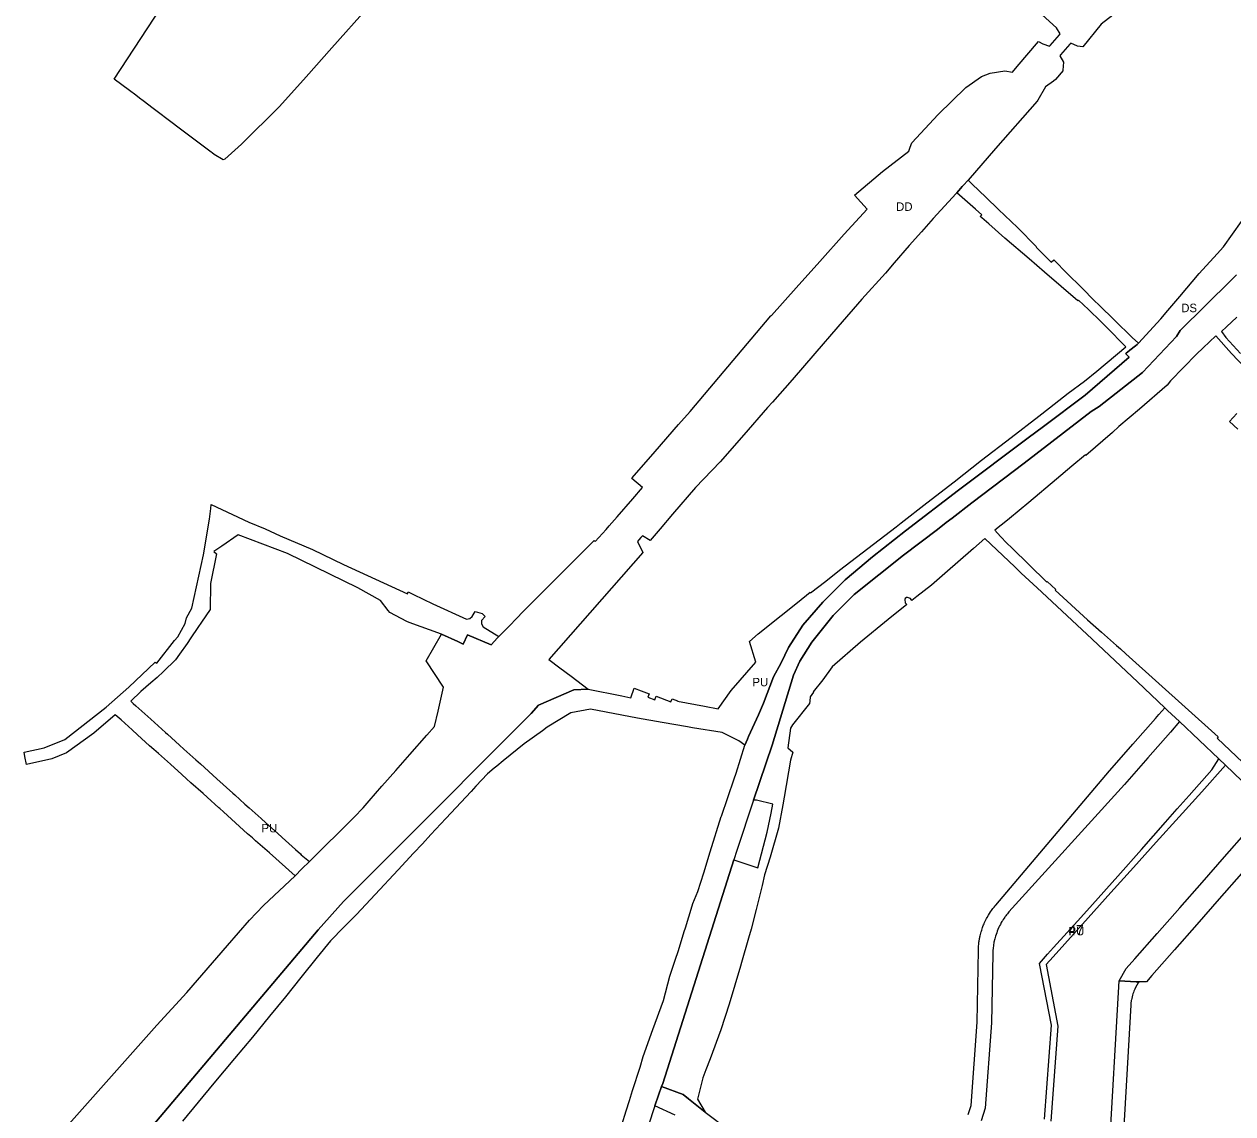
# Model space of a CAD drawing. Extents: x -537034 to -534353, y -1176562 to -1173176.
# Drawn here: x -536869 to -536157, y -1175906 to -1175264 of the extents above; entities that cross this region are included whole.
import ezdxf

# ---------------------------------------------------------------- set-up
doc = ezdxf.new("R2010")
doc.units = 0
for name, color, linetype in [('90320013', 7, 'Continuous'), ('90320023', 7, 'Continuous'), ('90330013', 7, 'Continuous'), ('90450013', 7, 'Continuous'), ('90450023', 7, 'Continuous'), ('ID_navrh', 7, 'Continuous')]:
    doc.layers.add(name, color=color, linetype=linetype)

msp = doc.modelspace()

# ---------------------------------------------------------------- linework, layer by layer
at = {"layer": '90320013'}
for points in [[(-536519.66, -1175920.91), (-536514.46, -1175904.33), (-536512.56, -1175898.3), (-536510.72, -1175892.44), (-536506.23, -1175878.56), (-536504.53, -1175872.39), (-536498.83, -1175856.51), (-536492.59, -1175839.22), (-536488.8, -1175824.91), (-536485.61, -1175815.62), (-536483.62, -1175809.83), (-536480.29, -1175798.68), (-536479.62, -1175796.43), (-536475.64, -1175783.55), (-536475.23, -1175782.21), (-536472.36, -1175775.09), (-536468.71, -1175764.01), (-536465.05, -1175751.7), (-536458.51, -1175730.84), (-536458.43, -1175730.59), (-536450.82, -1175708.65), (-536449.79, -1175705.35), (-536444.62, -1175688.79), (-536443.04, -1175685.26), (-536442.34, -1175683.69), (-536436.61, -1175670.86), (-536433.52, -1175663.95), (-536427.64, -1175648.47), (-536423.18, -1175640.21), (-536418.84, -1175631.19), (-536410.33, -1175618.03), (-536398.71, -1175604.41), (-536385.41, -1175591.37), (-536369.41, -1175577.67), (-536349.95, -1175562.45), (-536318.57, -1175538.4), (-536277.56, -1175507.64), (-536268.45, -1175500.89), (-536243.96, -1175482.32), (-536217.96, -1175459.97), (-536220.11, -1175458.05), (-536219.83, -1175457.6), (-536217.91, -1175456.09), (-536217.72, -1175455.94), (-536214.26, -1175453.22), (-536213.33, -1175452.49), (-536212.48, -1175451.82), (-536199.34, -1175437.32), (-536195.17, -1175432.47), (-536188.12, -1175424.25), (-536176.87, -1175410.74), (-536166.1, -1175399.03), (-536162.37, -1175394.92), (-536151.81, -1175379.91)], [(-536154.83, -1175411.41), (-536157.86, -1175414.59), (-536187.97, -1175444.22), (-536190.24, -1175447.73), (-536210.28, -1175468.95), (-536235.72, -1175489.07), (-536240.39, -1175492.07), (-536279.99, -1175522.59), (-536310.74, -1175545.81), (-536322.43, -1175554.85), (-536325.83, -1175557.48), (-536331.05, -1175561.51), (-536351.16, -1175576.73), (-536380.2, -1175599.97), (-536392.55, -1175612.31), (-536405.08, -1175628.03), (-536412.09, -1175639.32), (-536415.88, -1175647.57), (-536428.44, -1175688.76), (-536439.57, -1175721.17), (-536449.31, -1175750.95), (-536451.05, -1175756.43), (-536492.97, -1175888.35), (-536493.8, -1175890.01), (-536495.51, -1175895.12), (-536497.61, -1175901.43), (-536501.59, -1175913.34)]]:
    msp.add_lwpolyline(points, dxfattribs=at)
at = {"layer": '90320023'}
msp.add_lwpolyline([(-536666.61, -1175253.57), (-536687.97, -1175277.68), (-536703.1, -1175294.68), (-536718.93, -1175312.13), (-536741.24, -1175334.42), (-536751.07, -1175343.25), (-536752.13, -1175343.71), (-536757.4, -1175340.47), (-536758.57, -1175339.58), (-536759.2, -1175339.11), (-536765.49, -1175334.36), (-536770.11, -1175330.87), (-536779.51, -1175323.77), (-536781.4, -1175322.34), (-536793.39, -1175313.28), (-536799.27, -1175308.85), (-536801.44, -1175307.2), (-536803.58, -1175305.58), (-536807.23, -1175302.83), (-536816.28, -1175295.99), (-536776.99, -1175235.99)], dxfattribs=at)
at = {"layer": '90330013'}
for points in [[(-536846.2, -1175915.82), (-536791.26, -1175853.94), (-536773.58, -1175834.53), (-536749.56, -1175806.92), (-536736.63, -1175791.89), (-536728.37, -1175783.23), (-536709.68, -1175765.75), (-536705.63, -1175761.74), (-536701.22, -1175757.38), (-536674.81, -1175731.24), (-536669.64, -1175725.77), (-536666.05, -1175721.61), (-536658.6, -1175712.98), (-536650.32, -1175703.64), (-536642.03, -1175694.23), (-536632.12, -1175682.89), (-536627.48, -1175677.77), (-536625.43, -1175668.78), (-536622.16, -1175654.48), (-536632.47, -1175639.06), (-536623.43, -1175623.26), (-536613.76, -1175627.61), (-536610.57, -1175629.19), (-536607.97, -1175623.66), (-536594.17, -1175629.6), (-536590.32, -1175625.47), (-536589.63, -1175624.73), (-536582.21, -1175617.2), (-536580.31, -1175615.27), (-536574, -1175608.87), (-536533.39, -1175568.16), (-536532.78, -1175568.71), (-536526.41, -1175561.66), (-536524.48, -1175559.53), (-536521.41, -1175555.97), (-536519.88, -1175554.19), (-536510.62, -1175543.44), (-536504.9, -1175536.8), (-536511.29, -1175531.46), (-536511.02, -1175531.18), (-536497.42, -1175515.55), (-536483.59, -1175499.65), (-536476.88, -1175491.96), (-536429.2, -1175435.56), (-536428.82, -1175435.33), (-536414.4, -1175419.11), (-536400.46, -1175403.61), (-536385.98, -1175387.51), (-536372.45, -1175372.79), (-536379.99, -1175364.45), (-536363.36, -1175350.59), (-536348.02, -1175338.47), (-536347.12, -1175336.1), (-536346.17, -1175333.57), (-536330.65, -1175316.94), (-536314.41, -1175300.96), (-536305.13, -1175294.43), (-536299.98, -1175292.46), (-536291.26, -1175291.15), (-536286.76, -1175291.86), (-536284.03, -1175288.64), (-536271.52, -1175273.92), (-536269.03, -1175275.21), (-536265.02, -1175276.59), (-536264.68, -1175276.25), (-536259.12, -1175269.87), (-536258.63, -1175269.32), (-536260.91, -1175265.77), (-536271.48, -1175256.23)], [(-536227.77, -1175258.32), (-536234.54, -1175263.73), (-536245.43, -1175277.08), (-536248.56, -1175276.64), (-536252.42, -1175274.85), (-536252.93, -1175275.41), (-536258.45, -1175281.76), (-536258.98, -1175282.35), (-536256.81, -1175285.98), (-536257.21, -1175290.77), (-536256.94, -1175290.98), (-536261.38, -1175296.33), (-536262.6, -1175297.2), (-536267.4, -1175300.62), (-536271.83, -1175308.52), (-536272.24, -1175308.98), (-536296.79, -1175336.88), (-536313.02, -1175355.71), (-536315.99, -1175358.85), (-536316.44, -1175359.37), (-536318.47, -1175361.7), (-536319.66, -1175363.06), (-536320, -1175363.42), (-536333.58, -1175378.3), (-536340.48, -1175386.07), (-536347.65, -1175394.16), (-536356.49, -1175404.43), (-536361.6, -1175410.37), (-536375.55, -1175425.83), (-536389.71, -1175442.02), (-536403.38, -1175457.84), (-536416.7, -1175473.42), (-536428.33, -1175486.62), (-536431.21, -1175489.75), (-536445.18, -1175505.86), (-536459.13, -1175521.73), (-536473.75, -1175536.92), (-536487.22, -1175552.59), (-536494.58, -1175561.14), (-536500.44, -1175568.03), (-536504.84, -1175565.28), (-536505.83, -1175566.38), (-536507.02, -1175567.7), (-536507.91, -1175568.69), (-536504.76, -1175575.16), (-536560.04, -1175638.23), (-536553.54, -1175643.15), (-536547.03, -1175648.06), (-536536.94, -1175655.74), (-536545.35, -1175656.1), (-536566.3, -1175665.09), (-536570.53, -1175670.13), (-536586.48, -1175686.06), (-536635.97, -1175735.72), (-536681.17, -1175780.92), (-536696.11, -1175797.67), (-536798.9, -1175919.35)]]:
    msp.add_lwpolyline(points, dxfattribs=at)
at = {"layer": '90450013'}
for points in [[(-536798.9, -1175919.35), (-536696.11, -1175797.67), (-536681.17, -1175780.92), (-536635.97, -1175735.72), (-536586.48, -1175686.06), (-536570.53, -1175670.13), (-536566.3, -1175665.09), (-536545.35, -1175656.1), (-536536.94, -1175655.74), (-536517.13, -1175659.73), (-536511.84, -1175660.79), (-536509.74, -1175655.18), (-536505.74, -1175656.72), (-536501.02, -1175658.45), (-536501.75, -1175660.46), (-536497.69, -1175661.96), (-536496.94, -1175659.94), (-536488.15, -1175663.14), (-536487.36, -1175661.38), (-536484.19, -1175662.58), (-536484.22, -1175662.75), (-536468.28, -1175665.81), (-536460.22, -1175667.35), (-536452.58, -1175656.54), (-536438.2, -1175639.85), (-536441.85, -1175627.58), (-536436.79, -1175623.18), (-536423.27, -1175612.27), (-536413.63, -1175604.6), (-536406.06, -1175598.58), (-536405.88, -1175599.04), (-536396.81, -1175592.01), (-536388.78, -1175585.64), (-536372.09, -1175572.8), (-536355.44, -1175559.96), (-536352.38, -1175557.58), (-536337.3, -1175545.98), (-536321.26, -1175533.57), (-536305.05, -1175520.71), (-536287.61, -1175507.42), (-536271.22, -1175494.78), (-536265.06, -1175489.95), (-536253.95, -1175481.24), (-536244.48, -1175474.06), (-536237.18, -1175468.25), (-536220.03, -1175453.93), (-536222.14, -1175451.77), (-536229.53, -1175444.21), (-536234.79, -1175438.94), (-536242.05, -1175431.84), (-536247.92, -1175426.47), (-536248.3, -1175426.83), (-536267.93, -1175409.82), (-536276.93, -1175402.02), (-536291.35, -1175389.78), (-536300.73, -1175381.3), (-536304.93, -1175377.81), (-536305.8, -1175377.11), (-536304.81, -1175376.15), (-536308.59, -1175372.82), (-536319.66, -1175363.06), (-536318.47, -1175361.7), (-536316.44, -1175359.37), (-536315.99, -1175358.85), (-536313.02, -1175355.71), (-536310.63, -1175358.07), (-536302.54, -1175365.62), (-536295.1, -1175372.83), (-536283.95, -1175383.63), (-536272.71, -1175395.02), (-536272.91, -1175395.19), (-536263.98, -1175403.91), (-536262.48, -1175402.52), (-536254.37, -1175410.87), (-536246.41, -1175418.7), (-536245.74, -1175419.37), (-536238.66, -1175426.53), (-536235.8, -1175429.32), (-536226.72, -1175438.18), (-536216.31, -1175448.44), (-536212.48, -1175451.82), (-536213.33, -1175452.49), (-536214.26, -1175453.22), (-536217.72, -1175455.94), (-536217.91, -1175456.09), (-536219.83, -1175457.6), (-536220.11, -1175458.05), (-536217.96, -1175459.97), (-536243.96, -1175482.32), (-536268.45, -1175500.89), (-536277.56, -1175507.64), (-536318.57, -1175538.4), (-536349.95, -1175562.45), (-536369.41, -1175577.67), (-536385.41, -1175591.37), (-536398.71, -1175604.41), (-536410.33, -1175618.03), (-536418.84, -1175631.19), (-536423.18, -1175640.21), (-536427.64, -1175648.47), (-536433.52, -1175663.95), (-536436.61, -1175670.86), (-536442.34, -1175683.69), (-536443.04, -1175685.26), (-536444.62, -1175688.79), (-536448.08, -1175686.22), (-536457.91, -1175681.22), (-536475.34, -1175678.45), (-536478.39, -1175677.96), (-536493.26, -1175675.35), (-536507.93, -1175672.77), (-536535.65, -1175667.47), (-536547.15, -1175669.72), (-536561.06, -1175678.16), (-536563.89, -1175680.22), (-536574.63, -1175688.07), (-536587.03, -1175697.96), (-536590.8, -1175701.08), (-536592.36, -1175702.37), (-536596.27, -1175705.6), (-536603.11, -1175712.96), (-536605.99, -1175716.06), (-536620.82, -1175732.03), (-536629.61, -1175741.5), (-536634.65, -1175746.92), (-536639.8, -1175752.47), (-536648.87, -1175762.23), (-536662.43, -1175776.83), (-536673.39, -1175788.63), (-536678.56, -1175793.79), (-536682.84, -1175798.07), (-536686.9, -1175802.13), (-536688.89, -1175804.11), (-536696.58, -1175813.74), (-536706.21, -1175825.8), (-536715.29, -1175837.15), (-536724.7, -1175848.63), (-536734.85, -1175860.84), (-536745.41, -1175873.54), (-536757.5, -1175888.08), (-536766.77, -1175899.23), (-536776.04, -1175910.38)], [(-536137.07, -1175723.72), (-536161.26, -1175700.56), (-536165.13, -1175696.86), (-536188.42, -1175674.83), (-536195.39, -1175668.24), (-536197.03, -1175666.69), (-536213.24, -1175651.35), (-536242.96, -1175623.24), (-536272.28, -1175596.08), (-536281.78, -1175587.31), (-536285.38, -1175583.66), (-536303.1, -1175566.86), (-536309.84, -1175572.9), (-536326.67, -1175587.47), (-536334.66, -1175594.33), (-536343.13, -1175601.15), (-536346.06, -1175603.45), (-536346.95, -1175602.29), (-536348.75, -1175601.63), (-536349.29, -1175601.72), (-536350.06, -1175602.36), (-536350.29, -1175602.89), (-536350.09, -1175604.75), (-536349.14, -1175605.89), (-536360.15, -1175614.65), (-536376.48, -1175628.12), (-536393.04, -1175642.64), (-536398.67, -1175650.18), (-536404.31, -1175657.23), (-536404.05, -1175657.58), (-536406.12, -1175660.23), (-536406.33, -1175662.83), (-536406.45, -1175664.29), (-536416.48, -1175676.82), (-536417.58, -1175678.72), (-536419.26, -1175690.31), (-536416.33, -1175692.99), (-536417.59, -1175697.58), (-536421.44, -1175719.49), (-536422.23, -1175723.99), (-536424.7, -1175737.67), (-536429.73, -1175754.77), (-536433.07, -1175765.28), (-536434.3, -1175771.54), (-536437.89, -1175785.71), (-536440.93, -1175797.21), (-536442.34, -1175802.56), (-536446.58, -1175817), (-536447.2, -1175819.1), (-536453.87, -1175841.56), (-536458.78, -1175856.58), (-536465.03, -1175873.79), (-536467.59, -1175880.27), (-536469.41, -1175884.86), (-536470.92, -1175891.24), (-536472.39, -1175897.49), (-536467.96, -1175905.16), (-536477.8, -1175897.3), (-536480.96, -1175894.78), (-536493.8, -1175890.01), (-536492.97, -1175888.35), (-536451.05, -1175756.43), (-536436.96, -1175761.16), (-536431.49, -1175740.04), (-536429.1, -1175728.93), (-536428.05, -1175723.51), (-536437.66, -1175721.11), (-536439.57, -1175721.17), (-536428.44, -1175688.76), (-536415.88, -1175647.57), (-536412.09, -1175639.32), (-536405.08, -1175628.03), (-536392.55, -1175612.31), (-536380.2, -1175599.97), (-536351.16, -1175576.73), (-536331.05, -1175561.51), (-536325.83, -1175557.48), (-536322.43, -1175554.85), (-536310.74, -1175545.81), (-536279.99, -1175522.59), (-536240.39, -1175492.07), (-536235.72, -1175489.07), (-536210.28, -1175468.95), (-536190.24, -1175447.73), (-536187.97, -1175444.22), (-536157.86, -1175414.59), (-536154.83, -1175411.41)], [(-536154.62, -1175436.42), (-536160.63, -1175442.04), (-536163.57, -1175444.87), (-536161.02, -1175448.4), (-536152.52, -1175457.9)], [(-536145.9, -1175470.18), (-536157.81, -1175457.83), (-536166.96, -1175447.43), (-536174.37, -1175454.52), (-536178.34, -1175458.15), (-536193.76, -1175473.93), (-536195.57, -1175476.41), (-536212.02, -1175490.57), (-536224.18, -1175500.97), (-536227.97, -1175504.42), (-536243.58, -1175517.91), (-536243.83, -1175517.63), (-536251.86, -1175524.3), (-536260.88, -1175531.83), (-536277.28, -1175545.71), (-536288.67, -1175555.08), (-536289.84, -1175556.05), (-536297.26, -1175561.99), (-536293.97, -1175565.69), (-536290.17, -1175569.66), (-536287.29, -1175572.46), (-536266.71, -1175592.48), (-536266.4, -1175592.18), (-536261.26, -1175596.93), (-536261.61, -1175597.28), (-536242.55, -1175614.82), (-536234.33, -1175622.13), (-536225.43, -1175630.05), (-536223.22, -1175632.01), (-536220.01, -1175634.87), (-536165.54, -1175683.92), (-536166.27, -1175684.73), (-536135.96, -1175713.3)], [(-536153.95, -1175502.45), (-536158.95, -1175497.88), (-536154.68, -1175493.22)], [(-536151.76, -1175764.43), (-536164.97, -1175779.44), (-536178.18, -1175794.46), (-536191.39, -1175809.48), (-536204.6, -1175824.5), (-536207.91, -1175828.28), (-536212.4, -1175828.28), (-536213.92, -1175828.28), (-536223.98, -1175827.73), (-536219.75, -1175820.53), (-536214.67, -1175814.75), (-536201.46, -1175799.73), (-536188.25, -1175784.71), (-536175.04, -1175769.7), (-536161.83, -1175754.68), (-536148.62, -1175739.66)]]:
    msp.add_lwpolyline(points, dxfattribs=at)
msp.add_lwpolyline([(-536759.14, -1175546.95), (-536746.47, -1175552.78), (-536736.91, -1175557.23), (-536727.32, -1175561.29), (-536718.49, -1175565.39), (-536699.5, -1175573.46), (-536681.23, -1175582.22), (-536662.36, -1175590.8), (-536643.39, -1175599.45), (-536642.94, -1175598.37), (-536639.79, -1175599.9), (-536628.44, -1175605.4), (-536608.62, -1175614.38), (-536606.62, -1175614.07), (-536605.3, -1175612.9), (-536603.52, -1175610.04), (-536599.34, -1175611.14), (-536597.56, -1175612.88), (-536599.82, -1175615.2), (-536599.89, -1175617.24), (-536598.9, -1175619.06), (-536589.63, -1175624.73), (-536590.32, -1175625.47), (-536594.17, -1175629.6), (-536607.97, -1175623.66), (-536610.57, -1175629.19), (-536613.76, -1175627.61), (-536623.43, -1175623.26), (-536642.39, -1175616.44), (-536643.86, -1175615.91), (-536653.91, -1175610.57), (-536654.82, -1175609.37), (-536659.38, -1175603.38), (-536672.73, -1175595.94), (-536714.23, -1175575.68), (-536743.31, -1175564.8), (-536752.82, -1175571.39), (-536756.99, -1175574.28), (-536757.55, -1175574.67), (-536756.05, -1175575.87), (-536759.54, -1175593.44), (-536759.8, -1175608.87), (-536764.75, -1175616.19), (-536766.93, -1175619.43), (-536771.12, -1175625.57), (-536773.32, -1175628.81), (-536777.81, -1175635.2), (-536780.16, -1175638.55), (-536787.27, -1175645.35), (-536791.04, -1175648.95), (-536794.76, -1175652.08), (-536800.66, -1175657.18), (-536806.57, -1175662.74), (-536806.21, -1175663.08), (-536805.07, -1175664.17), (-536803.64, -1175665.54), (-536794.65, -1175673.53), (-536786.11, -1175681.27), (-536784.91, -1175682.36), (-536777.74, -1175688.84), (-536775.31, -1175691.04), (-536768.18, -1175697.45), (-536765.5, -1175699.86), (-536755.85, -1175708.53), (-536746.34, -1175717.05), (-536745.23, -1175718.05), (-536739.26, -1175723.46), (-536736.75, -1175725.73), (-536729.73, -1175731.96), (-536726.9, -1175734.47), (-536720.11, -1175740.64), (-536717.27, -1175743.22), (-536709.35, -1175750.36), (-536706.53, -1175752.91), (-536706, -1175753.35), (-536701.22, -1175757.38), (-536705.63, -1175761.74), (-536709.68, -1175765.75), (-536724.85, -1175752.34), (-536732.94, -1175745.15), (-536734.85, -1175743.46), (-536737.64, -1175740.95), (-536744.77, -1175734.51), (-536751.87, -1175728.12), (-536754.12, -1175726.09), (-536754.56, -1175725.69), (-536761.41, -1175719.51), (-536763.88, -1175717.28), (-536771.05, -1175710.94), (-536773.69, -1175708.6), (-536776.41, -1175706.14), (-536783.16, -1175700.01), (-536790.25, -1175693.76), (-536792.96, -1175691.36), (-536795.41, -1175689.13), (-536802.59, -1175682.62), (-536805.72, -1175679.78), (-536812.27, -1175673.86), (-536815.65, -1175670.79), (-536828.39, -1175681.76), (-536844.44, -1175693.33), (-536853.12, -1175696.82), (-536868.06, -1175700.18), (-536868.9, -1175695.44), (-536869.36, -1175692.85), (-536857.62, -1175690.33), (-536845.3, -1175685.5), (-536820.95, -1175666.33), (-536807.7, -1175654.66), (-536792.15, -1175639.9), (-536791.22, -1175640.34), (-536780.67, -1175627.12), (-536778.85, -1175624.83), (-536774.37, -1175617.09), (-536773.63, -1175613.72), (-536770.63, -1175607.96), (-536763.62, -1175576.6), (-536760.2, -1175555.61), (-536759.43, -1175549.31)], close=True, dxfattribs=at)
at = {"layer": '90450023'}
for points in [[(-536312.97, -1175906.6), (-536311.28, -1175901.27), (-536307.6, -1175852.12), (-536306.92, -1175809.71), (-536306.87, -1175808.15), (-536306.8, -1175807.11), (-536306.73, -1175806.24), (-536306.67, -1175805.67), (-536306.57, -1175804.95), (-536306.48, -1175804.34), (-536306.43, -1175803.99), (-536306.38, -1175803.68), (-536306.33, -1175803.37), (-536306.29, -1175803.14), (-536306.25, -1175802.9), (-536306.18, -1175802.58), (-536306.14, -1175802.36), (-536306.01, -1175801.72), (-536305.89, -1175801.15), (-536305.71, -1175800.41), (-536305.49, -1175799.56), (-536305.3, -1175798.88), (-536305.16, -1175798.39), (-536304.98, -1175797.81), (-536304.73, -1175797.03), (-536304.48, -1175796.3), (-536304.21, -1175795.6), (-536303.87, -1175794.76), (-536303.6, -1175794.06), (-536303.23, -1175793.24), (-536302.89, -1175792.51), (-536302.49, -1175791.74), (-536302.12, -1175790.97), (-536301.76, -1175790.33), (-536300.99, -1175788.97), (-536300.46, -1175788.11), (-536299.78, -1175787.1), (-536299.15, -1175786.17), (-536298.37, -1175785.13), (-536297.65, -1175784.24), (-536297.04, -1175783.49), (-536296.62, -1175783.01), (-536294.42, -1175780.5), (-536229.68, -1175703.83), (-536222.67, -1175695.86), (-536215.87, -1175688.12), (-536202.53, -1175672.95), (-536200.54, -1175670.68), (-536197.03, -1175666.69), (-536195.39, -1175668.24), (-536188.42, -1175674.83), (-536193.66, -1175681.03), (-536207.02, -1175696.23), (-536213.86, -1175704.01), (-536220.84, -1175711.96), (-536288.9, -1175787.09), (-536289.38, -1175787.65), (-536289.79, -1175788.15), (-536290.29, -1175788.77), (-536290.76, -1175789.38), (-536291.11, -1175789.86), (-536291.39, -1175790.25), (-536291.8, -1175790.84), (-536292.31, -1175791.61), (-536292.73, -1175792.26), (-536293.05, -1175792.81), (-536293.43, -1175793.42), (-536293.97, -1175794.42), (-536294.4, -1175795.26), (-536294.83, -1175796.15), (-536295.38, -1175797.39), (-536295.77, -1175798.37), (-536296.15, -1175799.37), (-536296.85, -1175801.48), (-536297.28, -1175802.91), (-536297.74, -1175804.95), (-536298.03, -1175806.8), (-536298.28, -1175808.45), (-536298.4, -1175809.88), (-536298.44, -1175811.27), (-536298.45, -1175811.87), (-536299.11, -1175852.5), (-536302.88, -1175902.89), (-536305.21, -1175910.23)], [(-536267.94, -1175909.34), (-536263.78, -1175853.79), (-536270.96, -1175817.48), (-536266.24, -1175812.05), (-536262.71, -1175808.04), (-536246.52, -1175790.3), (-536239.66, -1175782.64), (-536224.74, -1175766), (-536210.86, -1175750.28), (-536196.66, -1175734.2), (-536189.71, -1175726.32), (-536182.76, -1175718.44), (-536169.27, -1175703.26), (-536165.13, -1175696.86), (-536161.26, -1175700.56), (-536175.31, -1175716.19), (-536188.68, -1175731.06), (-536202.05, -1175745.94), (-536215.42, -1175760.82), (-536228.79, -1175775.69), (-536242.16, -1175790.56), (-536262.79, -1175813.53), (-536266.93, -1175818.13), (-536260.12, -1175854.47), (-536264.32, -1175910.46)], [(-536229.98, -1175933.36), (-536223.98, -1175827.73), (-536213.92, -1175828.28), (-536212.4, -1175828.28), (-536212.82, -1175828.99), (-536213.48, -1175830.29), (-536214.25, -1175831.68), (-536214.75, -1175832.69), (-536215.21, -1175833.72), (-536215.55, -1175834.59), (-536215.86, -1175835.47), (-536216.1, -1175836.25), (-536216.38, -1175837.24), (-536216.58, -1175838.11), (-536216.76, -1175838.99), (-536216.83, -1175839.39), (-536216.89, -1175839.79), (-536216.94, -1175840.18), (-536216.99, -1175840.53), (-536217.02, -1175840.78), (-536217.05, -1175841.07), (-536217.08, -1175841.39), (-536217.11, -1175841.79), (-536217.13, -1175842.13), (-536222.55, -1175937.44)], [(-536485.64, -1175906.89), (-536497.61, -1175901.43), (-536495.51, -1175895.12), (-536493.8, -1175890.01), (-536480.96, -1175894.78), (-536477.8, -1175897.3), (-536467.96, -1175905.16), (-536454.41, -1175915.38)]]:
    msp.add_lwpolyline(points, dxfattribs=at)

# ---------------------------------------------------------------- texts
at = {"layer": '90320013'}
msp.add_text('DS', height=5, rotation=0, dxfattribs=at).set_placement((-536187.35, -1175433.47))
at = {"layer": '90330013'}
msp.add_text('DD', height=5, rotation=360, dxfattribs=at).set_placement((-536355.4, -1175373.73))
at = {"layer": '90450013'}
for p in [(-536440.12, -1175654.08), (-536729.49, -1175740.19)]:
    msp.add_text('PU', height=5, rotation=360, dxfattribs=at).set_placement(p)
at = {"layer": '90450023'}
msp.add_text('PU', height=5, rotation=0, dxfattribs=at).set_placement((-536253.79, -1175800.89))
at = {"layer": 'ID_navrh'}
msp.add_text('47', height=6, rotation=0, dxfattribs=at).set_placement((-536253.79, -1175800.89))

doc.saveas('drawing.dxf')
